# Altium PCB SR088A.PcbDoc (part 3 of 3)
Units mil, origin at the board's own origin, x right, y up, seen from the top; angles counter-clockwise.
Board outline 5010 x 3800 mil, 6 copper layers (Top Layer, Signal Layer 1, Signal Layer 2, Signal Layer 3, Signal Layer 4, Bottom Layer), stack 61.4 mil thick; 199 components, 82 nets, 478 pads, 1347 vias.
Unrouted connection lines stored in the file: 13.
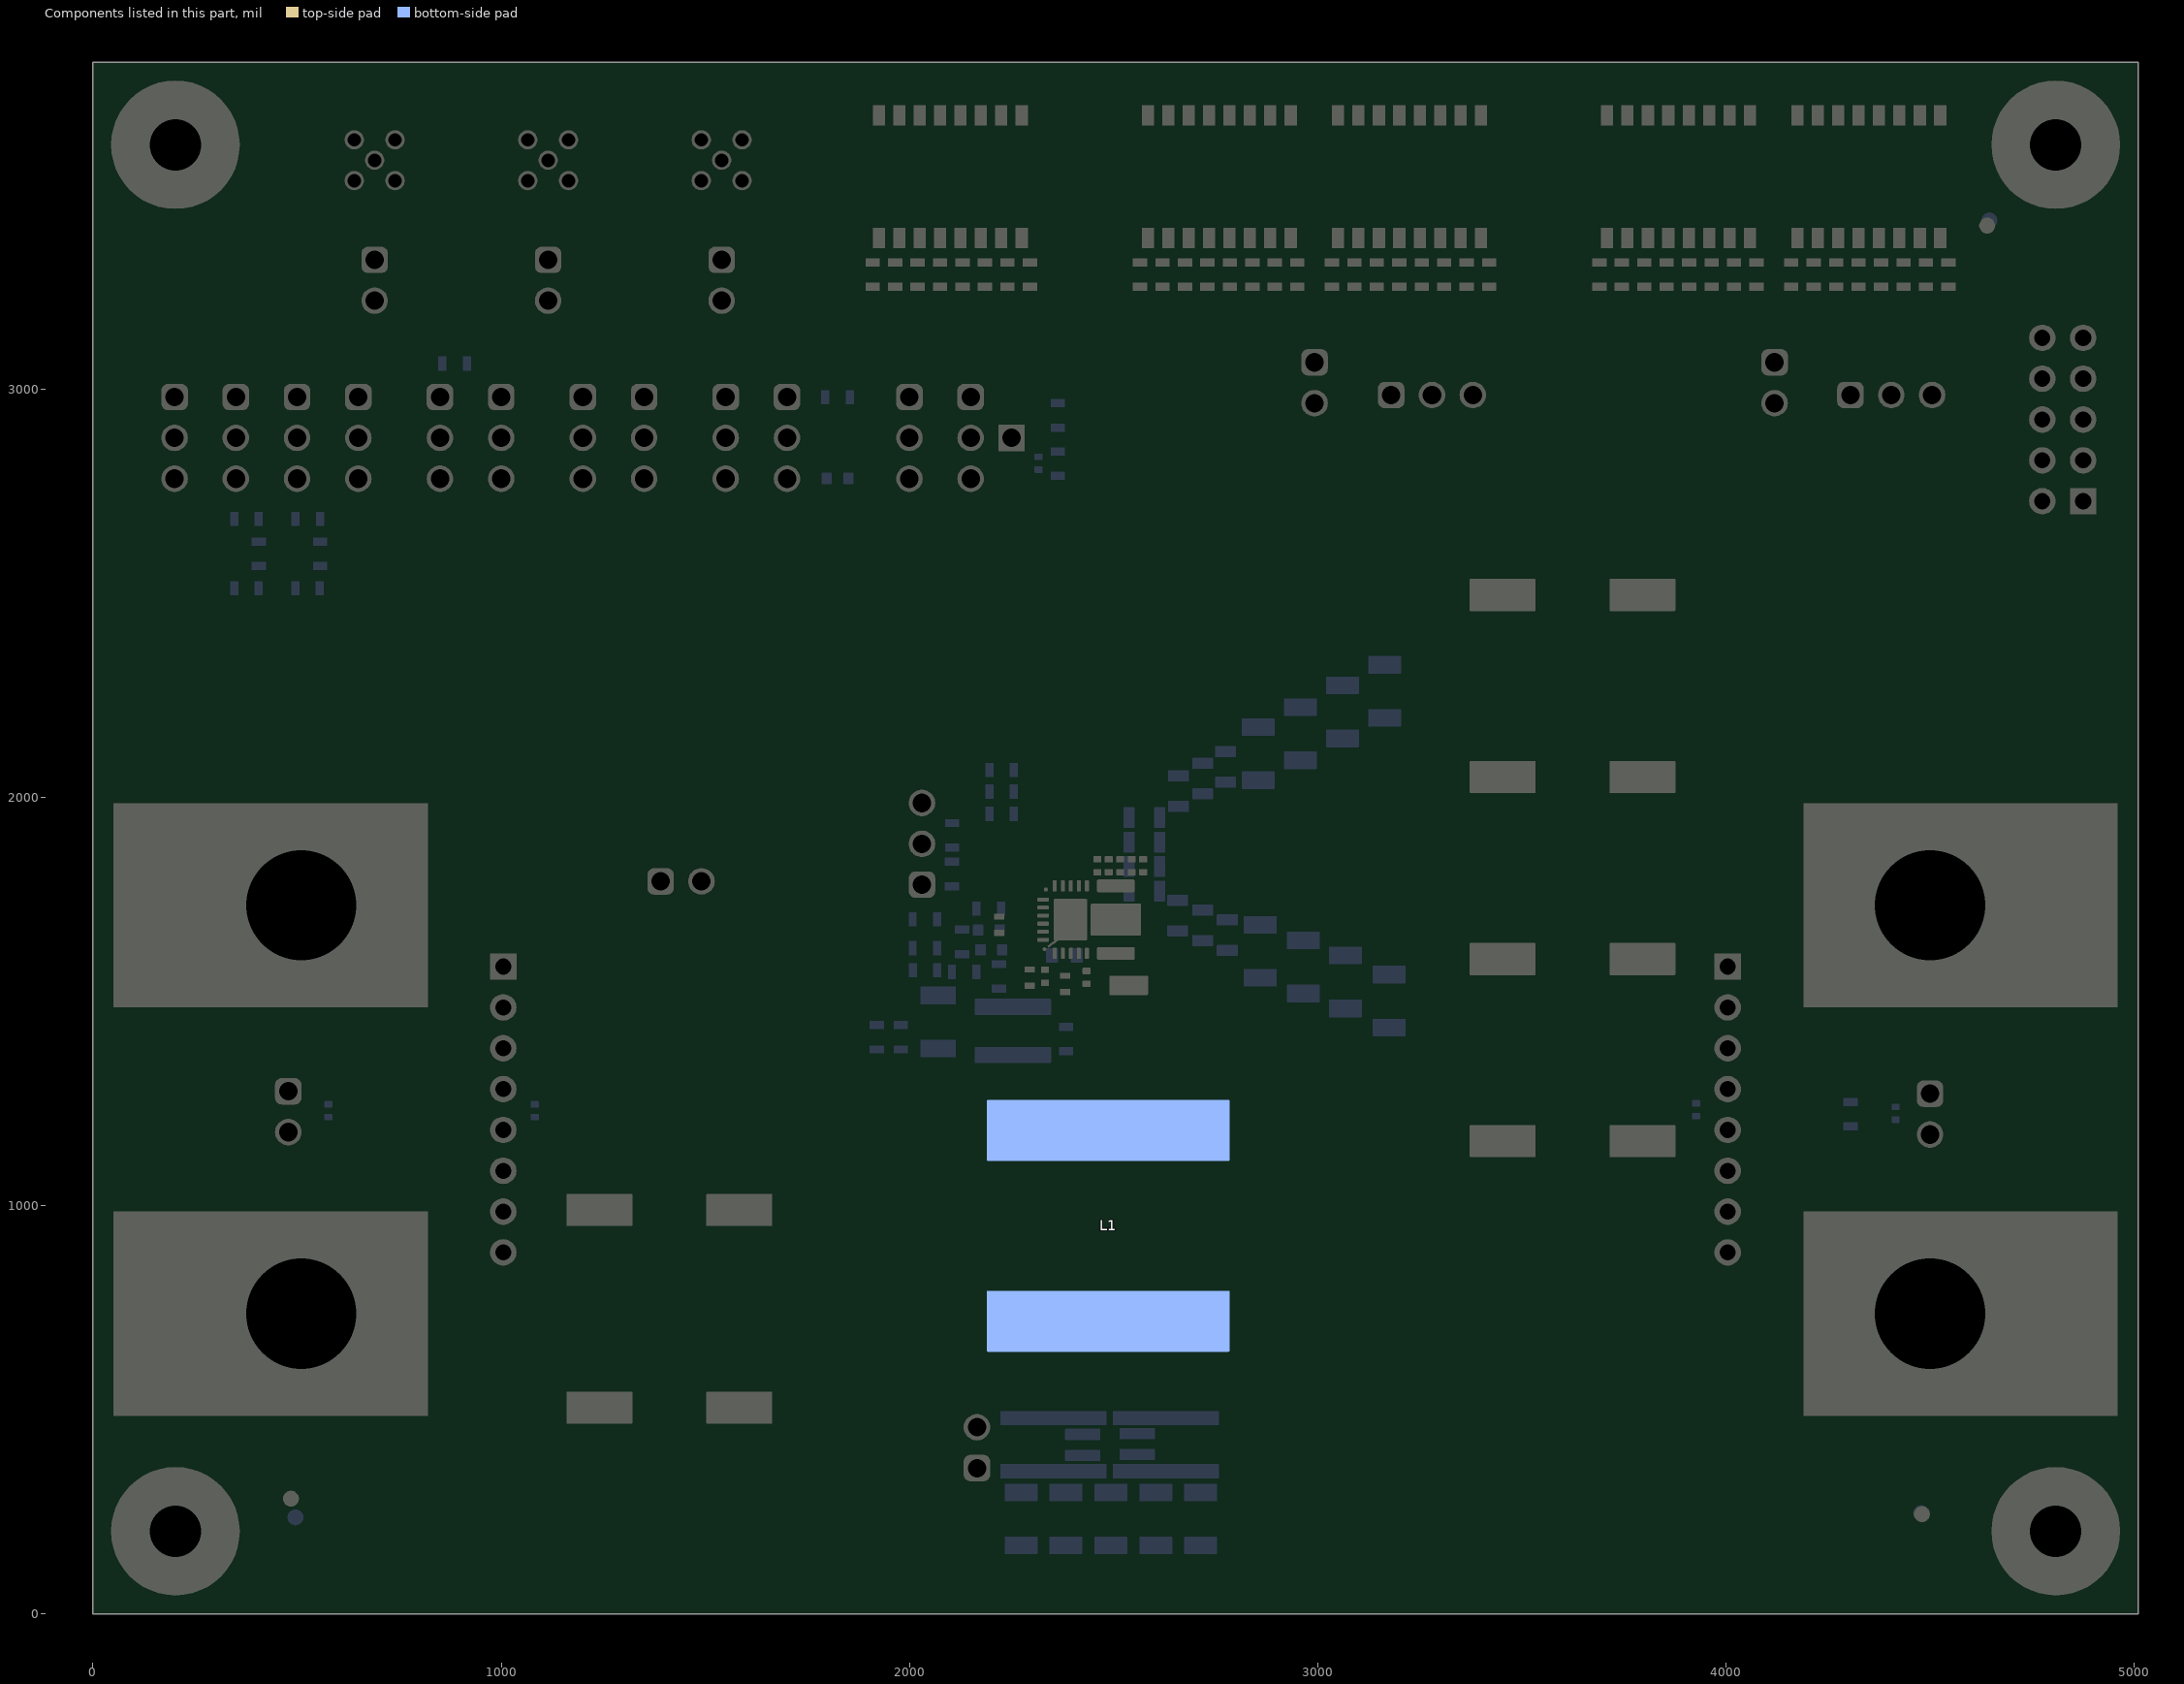
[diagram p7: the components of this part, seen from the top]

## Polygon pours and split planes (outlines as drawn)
AGND on Top Layer "TOP_LAYER_AGND_P178" (solid, remove dead copper, pour order 178): 2314.29,1632.94 2447.34,1632.22 2447.33,1536.55 2389.18,1478.22 2359.27,1478.19 2219.76,1338.59 1912.05,1338.59 1858.81,1391.83 1858.81,1623.43 1678.18,1804.07 1678.18,2015.39 1261.32,2432.24 25.49,2432.24 25.49,3774.23 4990.16,3774.23 4990.16,2670.21 2772.6,2670.21 2429.5,2327.11 2429.5,2024.51 2398.1,2024.51 2398.1,1761.45 2351.88,1761.45 2351.88,1651.86 2346.23,1646.21 2314.37,1646.21
VIN on Top Layer "TOP_LAYER_VIN_P143" (solid, pour order 143): 1178.25,2194.88 1777.67,1595.46 1777.67,1377.86 2766.5,407.08 2766.5,244.27 2738.76,216.54 2220.2,216.54 1541.95,397.36 1398.41,540.9 1398.41,1006.12 1161.72,1242.81 888.28,1242.81 0.91,1242.82 0.91,2194.88
SW on Top Layer "TOP_LAYER_SW_P133" (solid, remove dead copper, pour order 133): 2459.13,1621.28 2469.06,1631.22 2551.47,1631.22 2607.96,1574.72 2786.89,1292.8 2787.25,1293.16 2786.89,1111.04 2779.61,1103.77 2194.46,1103.77 2187.06,1111.16 2187.06,1248.1 2356.39,1417.43 2356.39,1439.65 2367.42,1450.68 2389.28,1450.68 2459.13,1520.17
VOUT on Top Layer "Top Layer-VOUT" (solid, pour order 110): 3688.9,1237.61 5019.69,1238.06 5019.69,2411.42 3700.81,2411.42 3543.33,2568.9 3365.98,2568.9 3216.91,2283.46 2639.16,1994.38 2602.34,1940.62 2602.34,1837.46 2589.18,1824.3 2450.49,1824.3 2450.49,1757.83 2567.39,1757.83 2843.71,1640 3365.98,1089.25 3540.54,1089.25
PGND on Top Layer "TOP_LAYER_AGND_P479" (solid, pour order 189): 0,3796.3 5010,3796.3 5010,0 0,0
PGND on Bottom Layer "TOP_LAYER_AGND_P479" (solid, remove dead copper, pour order 184): 3.77,3757.78 5014.63,3757.78 5014.63,-42.22 3.77,-42.22
L1 on Bottom Layer "Bottom Layer-L1" (solid, remove dead copper, pour order 147): 3033.74,464.54 3110.93,464.54 3204.02,557.62 3204.02,968.95 3102.17,1070.79 1926.64,1071.8 2083.7,617.19 2135.03,445.48 2168.17,424.21 2731.87,424.21 2787.35,368.74 2787.35,324.91 2850.14,262.12 2957.19,262.12 3014.56,319.49 3014.56,432.28 2839.45,607.48 2890.79,607.48
VIN on Bottom Layer "BOTTOM_LAYER_VIN_P152" (solid, remove dead copper, pour order 152): 1646.51,1743.24 2114.89,443.97 2174.34,404.01 2726.66,404.01 2766.5,364.17 2766.5,244.44 2738.6,216.54 2221.45,216.54 1539.15,396.81 1398.41,537.55 1398.41,1003.38 1159.8,1241.13 0,1241.13 0,2198 1191.75,2198
VOUT on Bottom Layer "Bottom Layer-VOUT" (solid, remove dead copper, pour order 175): 4990.16,1235.59 4990.16,2411.42 3700.79,2411.42 3545.85,2566.35 3365.84,2566.35 3216.91,2283.46 2592.96,1973.17 2580.05,1930.67 2580.05,1749.82 2981.24,1599.76 2981.24,1597.94 3326.88,1470.47 3954.83,1235.59
AGND on Bottom Layer "BOTTOM_LAYER_AGND_P176" (solid, remove dead copper, pour order 176): 2344.69,1598.7 2291.42,1598.7 2281.98,1589.26 2281.98,1575.53 2232.44,1526 2146.6,1526 2146.6,1392.58 2083.25,1329.22 1882.44,1329.22 1638.54,1990.29 1196.6,2432.24 21.81,2432.24 21.81,3778.03 4999.45,3778.03 4999.45,2674.02 2781.9,2674.02 2438.8,2330.92 2438.79,1957.14 2384.3,1902.64 2384.3,1801.92 2344.69,1762.32
VOUT on Bottom Layer "BOTTOM_LAYER_VOUT_P177" (solid, remove dead copper, pour order 177): 4076.03,1400.68 4076.03,2071.03 4104.28,2099.28 5010,2099.28 5010,1376.26 4100.46,1376.26
PGND on Bottom Layer "BOTTOM_LAYER_PGND_P182" (solid, remove dead copper, pour order 182): 4072.19,398.27 4072.19,1065.8 4105.94,1099.54 5004,1099.54 5004,366.53 4103.93,366.53
VIN on Bottom Layer "BOTTOM_LAYER_VIN_P183" (solid, remove dead copper, pour order 183): 931.81,2057.73 931.81,1402.79 885.47,1356.46 0,1356.46 0,2089.47 900.07,2089.47
PGND on Bottom Layer "BOTTOM_LAYER_PGND_P186" (solid, remove dead copper, pour order 186): 2558.39,1869.05 2446.5,1869.05 2446.5,1841.17 2558.39,1841.17
PGND on Bottom Layer "BOTTOM_LAYER_PGND_P187" (solid, remove dead copper, pour order 187): 931.81,398.27 931.81,1058.28 890.55,1099.54 0,1099.54 0,366.53 900.07,366.53
no net on Bottom Layer "BOTTOM_LAYER_NONET_P208" (solid, remove dead copper, pour order 208): 2319.14,770.02 2320.97,768.19 2320.97,590.5
SW on Signal Layer 2 "SIGNAL_LAYER_2_SW_P242" (solid, remove dead copper, pour order 242): 2227.4,1249.09 2204.6,1249.09 2204.6,1119.17 2227.4,1119.17
SW on Signal Layer 2 "SIGNAL_LAYER_2_SW_P240" (solid, remove dead copper, pour order 240): 2770.21,1249.09 2747.41,1249.09 2747.41,1119.17 2770.21,1119.17
SW on Signal Layer 2 "SIGNAL_LAYER_2_SW_P238" (solid, remove dead copper, pour order 238): 2339.73,1249.09 2297.57,1249.09 2297.57,1119.17 2339.73,1119.17
SW on Signal Layer 2 "SIGNAL_LAYER_2_SW_P237" (solid, remove dead copper, pour order 237): 2452.19,1249.09 2410.03,1249.09 2410.03,1119.17 2452.19,1119.17
SW on Signal Layer 2 "SIGNAL_LAYER_2_SW_P236" (solid, remove dead copper, pour order 236): 2564.65,1249.09 2522.49,1249.09 2522.49,1119.17 2564.65,1119.17
SW on Signal Layer 2 "SIGNAL_LAYER_2_SW_P235" (solid, remove dead copper, pour order 235): 2677.11,1249.09 2634.95,1249.09 2634.95,1119.17 2677.11,1119.17
PGND on Signal Layer 2 "Signal Layer 2-PGND" (solid, pour order 245): 5019.69,0 5019.69,2647.64 2781.22,2647.64 2671.32,2537.73 2671.32,2087.95 2612.35,2028.99 2612.35,1827.8 2517.55,1733.01 2517.55,1411.37 2425.08,1318.9 2104.77,1318.9 2064.58,1278.71 2064.58,686.12 2143.22,607.48 2411.59,607.48 2551.42,467.65 2551.42,369.39 2517.55,335.53 2144.01,335.53 1855.14,624.4 1855.14,1394.74 1055,2194.88 0.91,2194.88 0.91,0
PGND on Signal Layer 2 "SIGNAL_LAYER_2_PGND_P251" (solid, remove dead copper, pour order 251): 2258.7,185.99 2258.7,139.2 2757.6,139.2 2757.6,185.99
AGND on Signal Layer 2 "TOP_LAYER_AGND_P479" (solid, pour order 256): 21.81,3800 5010,3800 5010,0 21.81,0
PGND on Signal Layer 2 "SIGNAL_LAYER_2_PGND_P252" (solid, remove dead copper, pour order 252): 2444.53,1865.98 2456.75,1878.21 2546.19,1878.21 2558.65,1865.74 2558.65,1847.97 2546.17,1835.48 2457.53,1835.52 2444.53,1848.52
VOUT on Signal Layer 2 "Bottom Layer-VOUT" (solid, pour order 244): 5013.07,1241.66 4019.61,1241.66 3951.93,1253.26 3694.01,1253.26 3524.8,1084.05 3388.55,1084.05 3352.68,1119.93 3352.92,2530.34 3383.28,2560.7 3538.16,2560.93 3706.7,2392.38 5010,2392.38
PGND on Signal Layer 2 "SIGNAL_LAYER_2_PGND_P253" (solid, remove dead copper, pour order 253): 4076.3,394.16 4076.3,1065.94 4109.91,1099.54 5004,1099.54 5004,369.96 4100.5,369.96
VOUT on Signal Layer 2 "SIGNAL_LAYER_2_VOUT_P254" (solid, remove dead copper, pour order 254): 4076.03,1400.68 4076.03,2071.03 4101.13,2096.13 5010,2096.13 5010,1376.26 4100.46,1376.26
PGND on Signal Layer 2 "SIGNAL_LAYER_2_PGND_P255" (solid, remove dead copper, pour order 255): 931.81,398.27 931.81,1062.07 894.34,1099.54 0,1099.54 0,371.19 904.73,371.19
VIN on Signal Layer 2 "SIGNAL_LAYER_2_VIN_P243" (solid, remove dead copper, pour order 243): 931.81,2057.73 931.81,1402.79 885.47,1356.46 0,1356.46 0,2089.47 900.07,2089.47
SW on Signal Layer 3 "SIGNAL_LAYER_3_SW_P218" (solid, remove dead copper, pour order 218): 2227.4,1249.09 2204.6,1249.09 2204.6,1119.17 2227.4,1119.17
SW on Signal Layer 3 "SIGNAL_LAYER_3_SW_P217" (solid, remove dead copper, pour order 217): 2770.21,1249.09 2747.41,1249.09 2747.41,1119.17 2770.21,1119.17
SW on Signal Layer 3 "SIGNAL_LAYER_3_SW_P216" (solid, remove dead copper, pour order 216): 2339.73,1249.09 2297.57,1249.09 2297.57,1119.17 2339.73,1119.17
SW on Signal Layer 3 "SIGNAL_LAYER_3_SW_P215" (solid, remove dead copper, pour order 215): 2452.19,1249.09 2410.03,1249.09 2410.03,1119.17 2452.19,1119.17
SW on Signal Layer 3 "SIGNAL_LAYER_3_SW_P214" (solid, remove dead copper, pour order 214): 2564.65,1249.09 2522.49,1249.09 2522.49,1119.17 2564.65,1119.17
SW on Signal Layer 3 "SIGNAL_LAYER_3_SW_P213" (solid, remove dead copper, pour order 213): 2677.11,1249.09 2634.95,1249.09 2634.95,1119.17 2677.11,1119.17
AGND on Signal Layer 3 "TOP_LAYER_AGND_P479" (solid, pour order 262): 0,3800 5010,3800 5010,0 0,0
PGND on Signal Layer 3 "Signal Layer 3-PGND" (solid, remove dead copper, pour order 258): 0.91,0 5019.69,0 5019.69,2647.64 2781.22,2647.64 2671.87,2538.29 2671.87,2098.99 2444.21,1871.34 2444.21,1766.6 2433.57,1755.95 2364.52,1755.95 2352.32,1743.76 2352.32,1655.76 2357.44,1650.65 2452.36,1650.65 2517.56,1585.45 2517.55,1413.38 2423.07,1318.9 2104.32,1318.9 2064.58,1279.16 2064.58,686.12 2143.22,607.48 2411.59,607.48 2551.42,467.65 2551.42,369.39 2517.55,335.53 2143.22,335.53 1855.14,623.61 1855.14,1394.74 1055,2194.88 0.91,2194.88
PGND on Signal Layer 3 "SIGNAL_LAYER_3_PGND_P259" (solid, remove dead copper, pour order 259): 2444.53,1865.98 2456.75,1878.21 2546.19,1878.21 2558.65,1865.74 2558.65,1847.97 2546.17,1835.48 2457.53,1835.52 2444.53,1848.52
PGND on Signal Layer 3 "SIGNAL_LAYER_3_PGND_P260" (solid, remove dead copper, pour order 260): 4076.66,393.8 4076.66,1067.08 4109.12,1099.54 5004,1099.54 5004,369.96 4100.5,369.96
VOUT on Signal Layer 3 "SIGNAL_LAYER_3_VOUT_P257" (solid, remove dead copper, pour order 257): 4076.03,1400.68 4076.03,2071.03 4104.28,2099.28 5010,2099.28 5010,1376.26 4100.46,1376.26
PGND on Signal Layer 3 "SIGNAL_LAYER_3_PGND_P261" (solid, remove dead copper, pour order 261): 931.81,398.27 931.81,1061.4 893.67,1099.54 0,1099.54 0,370.86 904.4,370.86
VIN on Signal Layer 3 "SIGNAL_LAYER_3_VIN_P219" (solid, remove dead copper, pour order 219): 931.81,2057.73 931.81,1402.79 885.47,1356.46 0,1356.46 0,2089.47 900.07,2089.47
SW on Signal Layer 4 "SIGNAL_LAYER_4_SW_P231" (solid, remove dead copper, pour order 231): 2227.4,1249.09 2204.6,1249.09 2204.6,1119.17 2227.4,1119.17
SW on Signal Layer 4 "SIGNAL_LAYER_4_SW_P230" (solid, remove dead copper, pour order 230): 2770.21,1249.09 2747.41,1249.09 2747.41,1119.17 2770.21,1119.17
SW on Signal Layer 4 "SIGNAL_LAYER_4_SW_P229" (solid, remove dead copper, pour order 229): 2339.73,1249.09 2297.57,1249.09 2297.57,1119.17 2339.73,1119.17
SW on Signal Layer 4 "SIGNAL_LAYER_4_SW_P228" (solid, remove dead copper, pour order 228): 2452.19,1249.09 2410.03,1249.09 2410.03,1119.17 2452.19,1119.17
SW on Signal Layer 4 "SIGNAL_LAYER_4_SW_P227" (solid, remove dead copper, pour order 227): 2564.65,1249.09 2522.49,1249.09 2522.49,1119.17 2564.65,1119.17
SW on Signal Layer 4 "SIGNAL_LAYER_4_SW_P226" (solid, remove dead copper, pour order 226): 2677.11,1249.09 2634.95,1249.09 2634.95,1119.17 2677.11,1119.17
AGND on Signal Layer 4 "SIGNAL_LAYER_4_AGND_P263" (solid, remove dead copper, pour order 263): 1588.09,2438.79 25.49,2438.79 25.49,3774.23 4990.16,3774.23 4990.16,2670.21 1819.51,2670.21
PGND on Signal Layer 4 "TOP_LAYER_AGND_P479" (solid, remove dead copper, pour order 268): 0,3800 5010,3800 5010,0 0,0
PGND on Signal Layer 4 "SIGNAL_LAYER_4_PGND_P264" (solid, remove dead copper, pour order 264): 4072.19,398.27 4072.19,1065.8 4105.94,1099.54 5004,1099.54 5004,366.53 4103.93,366.53
VOUT on Signal Layer 4 "SIGNAL_LAYER_4_VOUT_P265" (solid, remove dead copper, pour order 265): 4076.03,1400.68 4076.03,2071.03 4104.28,2099.28 5010,2099.28 5010,1376.26 4100.46,1376.26
PGND on Signal Layer 4 "SIGNAL_LAYER_4_PGND_P266" (solid, remove dead copper, pour order 266): 931.81,398.27 931.81,1062.85 895.12,1099.54 0,1099.54 0,366.53 900.07,366.53
VIN on Signal Layer 4 "SIGNAL_LAYER_4_VIN_P267" (solid, remove dead copper, pour order 267): 931.81,2057.73 931.81,1402.79 885.47,1356.46 0,1356.46 0,2089.47 900.07,2089.47
SW on Signal Layer 1 "SIGNAL_LAYER_1_SW_P155" (solid, remove dead copper, pour order 155): 2677.11,1249.09 2634.95,1249.09 2634.95,1119.17 2677.11,1119.17
SW on Signal Layer 1 "SIGNAL_LAYER_1_SW_P161" (solid, remove dead copper, pour order 161): 2564.65,1249.09 2522.49,1249.09 2522.49,1119.17 2564.65,1119.17
SW on Signal Layer 1 "SIGNAL_LAYER_1_SW_P169" (solid, remove dead copper, pour order 169): 2452.19,1249.09 2410.03,1249.09 2410.03,1119.17 2452.19,1119.17
SW on Signal Layer 1 "SIGNAL_LAYER_1_SW_P197" (solid, remove dead copper, pour order 197): 2339.73,1249.09 2297.57,1249.09 2297.57,1119.17 2339.73,1119.17
SW on Signal Layer 1 "SIGNAL_LAYER_1_SW_P202" (solid, remove dead copper, pour order 202): 2770.21,1249.09 2747.41,1249.09 2747.41,1119.17 2770.21,1119.17
SW on Signal Layer 1 "SIGNAL_LAYER_1_SW_P203" (solid, remove dead copper, pour order 203): 2227.4,1249.09 2204.6,1249.09 2204.6,1119.17 2227.4,1119.17
PGND on Signal Layer 1 "SIGNAL_LAYER_1_PGND_P246" (solid, remove dead copper, pour order 246): 2550.84,1878.48 2451.36,1878.48 2444.22,1871.34 2444.22,1766.6 2433.57,1755.95 2364.52,1755.95 2352.32,1743.76 2352.32,1655.76 2357.44,1650.65 2530.99,1650.65 2560.17,1679.83 2560.54,1868.79
PGND on Signal Layer 1 "Signal Layer 1-PGND" (solid, pour order 247): 5019.69,0 5019.69,2647.64 2781.22,2647.64 2672.9,2539.32 2672.9,2100.03 2444.21,1871.34 2444.21,1658.79 2517.56,1585.45 2517.55,1411.61 2424.84,1318.9 2104.32,1318.9 2064.58,1279.16 2064.58,686.12 2143.22,607.48 2411.59,607.48 2551.42,467.65 2551.42,369.39 2517.55,335.53 2141.21,335.53 1855.12,621.62 1855.51,1394.38 1055,2194.88 0.91,2194.88 0.91,0
PGND on Signal Layer 1 "SIGNAL_LAYER_1_PGND_P249" (solid, remove dead copper, pour order 249): 4075.5,394.96 4075.5,1069.11 4105.94,1099.54 5004,1099.54 5004,369.96 4100.5,369.96
VOUT on Signal Layer 1 "SIGNAL_LAYER_1_VOUT_P204" (solid, remove dead copper, pour order 204): 4076.66,1400.05 4076.66,2071.66 4104.28,2099.28 5010,2099.28 5010,1376.26 4100.46,1376.26
PGND on Signal Layer 1 "SIGNAL_LAYER_1_PGND_P248" (solid, remove dead copper, pour order 248): 931.81,398.27 931.81,1059.68 891.95,1099.54 0,1099.54 0,371.19 904.73,371.19
VIN on Signal Layer 1 "SIGNAL_LAYER_1_VIN_P210" (solid, remove dead copper, pour order 210): 931.81,2057.73 931.81,1402.79 885.47,1356.46 0,1356.46 0,2089.47 900.07,2089.47
AGND on Signal Layer 1 "TOP_LAYER_AGND_P479" (solid, pour order 250): 0,3800 5010,3800 5010,0 0,0

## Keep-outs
Keep-Out Layer:
  text ".Layer_Name" at 577,-858.49 h60

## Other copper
Top Layer:
  pour cut-out: 3960.85,1184.78 ccw(c4004.42,1184.78) 4004.42,1141.21 ccw(c4004.42,1184.78) 4047.98,1184.78 ccw(c4004.42,1184.78) 4004.42,1228.35 ccw(c4004.42,1184.78)
  pour cut-out: 3915.68,1218 ccw(c3938.68,1218) 3938.68,1195 ccw(c3938.68,1218) 3961.68,1218 ccw(c3938.68,1218) 3938.68,1241 ccw(c3938.68,1218)
  pour cut-out: 3915.65,1251.14 ccw(c3938.65,1251.14) 3938.65,1228.14 ccw(c3938.65,1251.14) 3961.65,1251.14 ccw(c3938.65,1251.14) 3938.65,1274.14 ccw(c3938.65,1251.14)
  pour cut-out: 3960.95,1284.91 ccw(c4004.52,1284.91) 4004.52,1241.35 ccw(c4004.52,1284.91) 4048.08,1284.91 ccw(c4004.52,1284.91) 4004.52,1328.48 ccw(c4004.52,1284.91)
  pour cut-out: 960.99,1184.8 ccw(c1004.56,1184.8) 1004.56,1141.23 ccw(c1004.56,1184.8) 1048.12,1184.8 ccw(c1004.56,1184.8) 1004.56,1228.37 ccw(c1004.56,1184.8)
  pour cut-out: 960.99,1284.8 ccw(c1004.56,1284.8) 1004.56,1241.23 ccw(c1004.56,1284.8) 1048.12,1284.8 ccw(c1004.56,1284.8) 1004.56,1328.37 ccw(c1004.56,1284.8)
  pour cut-out: 1059.35,1218.41 ccw(c1082.35,1218.41) 1082.35,1195.41 ccw(c1082.35,1218.41) 1105.35,1218.41 ccw(c1082.35,1218.41) 1082.35,1241.41 ccw(c1082.35,1218.41)
  pour cut-out: 1059.23,1251.41 ccw(c1082.23,1251.41) 1082.23,1228.41 ccw(c1082.23,1251.41) 1105.23,1251.41 ccw(c1082.23,1251.41) 1082.23,1274.41 ccw(c1082.23,1251.41)
  pour cut-out: -23,0 ccw(c0,0) 0,-23 ccw(c0,0) 23,0 ccw(c0,0) 0,23 ccw(c0,0)
  pour cut-out: 3964.55,1274.85 3937.18,1256.03 3957.27,1235.94 4037.13,1235.94 4016.72,1280.62
  pour cut-out: 2328.76,1628.83 2349.99,1628.83 2349.99,1626.6 2328.76,1626.6
  pour cut-out: 2439.29,1765.13 2439.29,1756.09 2356.91,1756.09 2351.88,1751.06 2351.88,1647.69 2343.55,1647.69 2343.55,1765.13
  pour cut-out: 2351.88,1650.71 2359.29,1643.3 2457.31,1643.3 2457.31,1631.73 2351.88,1631.73
  pour cut-out: 2232.63,1605.84 2220.36,1618.11 2233.07,1639.46 2233.07,1686.14 2281.96,1686.14 2281.96,1605.84
  pour cut-out: 2197.88,1698.55 2197.88,1684.74 2207.88,1674.75 2238.34,1674.75 2238.34,1698.43
  text ".Layer_Name" at 577,-858.49 h60
Signal Layer 1:
  pour cut-out: 3960.95,1284.91 ccw(c4004.52,1284.91) 4004.52,1241.35 ccw(c4004.52,1284.91) 4048.08,1284.91 ccw(c4004.52,1284.91) 4004.52,1328.48 ccw(c4004.52,1284.91)
  pour cut-out: 3960.85,1184.78 ccw(c4004.42,1184.78) 4004.42,1141.21 ccw(c4004.42,1184.78) 4047.98,1184.78 ccw(c4004.42,1184.78) 4004.42,1228.35 ccw(c4004.42,1184.78)
  pour cut-out: 3915.68,1218 ccw(c3938.68,1218) 3938.68,1195 ccw(c3938.68,1218) 3961.68,1218 ccw(c3938.68,1218) 3938.68,1241 ccw(c3938.68,1218)
  pour cut-out: 3915.65,1251.14 ccw(c3938.65,1251.14) 3938.65,1228.14 ccw(c3938.65,1251.14) 3961.65,1251.14 ccw(c3938.65,1251.14) 3938.65,1274.14 ccw(c3938.65,1251.14)
  pour cut-out: 960.99,1184.8 ccw(c1004.56,1184.8) 1004.56,1141.23 ccw(c1004.56,1184.8) 1048.12,1184.8 ccw(c1004.56,1184.8) 1004.56,1228.37 ccw(c1004.56,1184.8)
  pour cut-out: 1059.23,1251.41 ccw(c1082.23,1251.41) 1082.23,1228.41 ccw(c1082.23,1251.41) 1105.23,1251.41 ccw(c1082.23,1251.41) 1082.23,1274.41 ccw(c1082.23,1251.41)
  pour cut-out: 1059.35,1218.41 ccw(c1082.35,1218.41) 1082.35,1195.41 ccw(c1082.35,1218.41) 1105.35,1218.41 ccw(c1082.35,1218.41) 1082.35,1241.41 ccw(c1082.35,1218.41)
  pour cut-out: 4984.51,370.2 4984.51,25.49 4665.51,25.49 4665.51,120.7
  pour cut-out: 25.49,376.98 25.49,25.49 344.49,25.49 344.49,127.47
  text ".Layer_Name" at 577,-858.49 h60
Signal Layer 2:
  pour cut-out: 2212.37,182.05 ccw(c2235.37,182.05) 2235.37,159.05 ccw(c2235.37,182.05) 2258.37,182.05 ccw(c2235.37,182.05) 2235.37,205.05 ccw(c2235.37,182.05)
  pour cut-out: 3960.85,1184.78 ccw(c4004.42,1184.78) 4004.42,1141.21 ccw(c4004.42,1184.78) 4047.98,1184.78 ccw(c4004.42,1184.78) 4004.42,1228.35 ccw(c4004.42,1184.78)
  pour cut-out: 3960.95,1284.91 ccw(c4004.52,1284.91) 4004.52,1241.35 ccw(c4004.52,1284.91) 4048.08,1284.91 ccw(c4004.52,1284.91) 4004.52,1328.48 ccw(c4004.52,1284.91)
  pour cut-out: 3915.68,1218 ccw(c3938.68,1218) 3938.68,1195 ccw(c3938.68,1218) 3961.68,1218 ccw(c3938.68,1218) 3938.68,1241 ccw(c3938.68,1218)
  pour cut-out: 3915.65,1251.14 ccw(c3938.65,1251.14) 3938.65,1228.14 ccw(c3938.65,1251.14) 3961.65,1251.14 ccw(c3938.65,1251.14) 3938.65,1274.14 ccw(c3938.65,1251.14)
  pour cut-out: 960.99,1184.8 ccw(c1004.56,1184.8) 1004.56,1141.23 ccw(c1004.56,1184.8) 1048.12,1184.8 ccw(c1004.56,1184.8) 1004.56,1228.37 ccw(c1004.56,1184.8)
  pour cut-out: 1059.35,1218.41 ccw(c1082.35,1218.41) 1082.35,1195.41 ccw(c1082.35,1218.41) 1105.35,1218.41 ccw(c1082.35,1218.41) 1082.35,1241.41 ccw(c1082.35,1218.41)
  pour cut-out: 1059.23,1251.41 ccw(c1082.23,1251.41) 1082.23,1228.41 ccw(c1082.23,1251.41) 1105.23,1251.41 ccw(c1082.23,1251.41) 1082.23,1274.41 ccw(c1082.23,1251.41)
  pour cut-out: 3960.32,1184.8 ccw(c4003.89,1184.8) 4003.89,1141.23 ccw(c4003.89,1184.8) 4047.45,1184.8 ccw(c4003.89,1184.8) 4003.89,1228.37 ccw(c4003.89,1184.8)
  pour cut-out: 3969.31,1278.61 3952.84,1269.27 3922.43,1267.36 3907.65,1252.58 3907.65,1232.55 4004.19,1161.73 4060.53,1233.22 4027.26,1279.43
  pour cut-out: 2612.57,1858.54 2612.57,1997.01 2591.7,1997.07 2591.7,1841.57 2491.5,1741.08 2512.97,1709.01 2547.82,1709.01 2576.57,1732.27 2612.57,1732.27 2612.57,1828.9
  pour cut-out: 4984.51,370.2 4984.51,25.49 4665.51,25.49 4665.51,120.7
  pour cut-out: 25.49,376.98 25.49,25.49 344.49,25.49 344.49,127.47
  pour cut-out: 2365.8,1812.56 2312.11,1758.87 2312.11,1638.32 2329.34,1621.08 2329.34,1596.27 2330.04,1596.97 2360.93,1596.97 2360.93,1633.77 2361.11,1633.94 2346.09,1648.96 2346.09,1748.6 2387.32,1789.83 2387.32,1792.25
  pour cut-out: 2354.97,1754.88 2460.08,1754.88 2460.08,1640.99 2355.47,1640.99
  text ".Layer_Name" at 577,-858.49 h60
Signal Layer 3:
  pour cut-out: 3915.65,1251.14 ccw(c3938.65,1251.14) 3938.65,1228.14 ccw(c3938.65,1251.14) 3961.65,1251.14 ccw(c3938.65,1251.14) 3938.65,1274.14 ccw(c3938.65,1251.14)
  pour cut-out: 3915.68,1218 ccw(c3938.68,1218) 3938.68,1195 ccw(c3938.68,1218) 3961.68,1218 ccw(c3938.68,1218) 3938.68,1241 ccw(c3938.68,1218)
  pour cut-out: 3960.85,1184.78 ccw(c4004.42,1184.78) 4004.42,1141.21 ccw(c4004.42,1184.78) 4047.98,1184.78 ccw(c4004.42,1184.78) 4004.42,1228.35 ccw(c4004.42,1184.78)
  pour cut-out: 3960.95,1284.91 ccw(c4004.52,1284.91) 4004.52,1241.35 ccw(c4004.52,1284.91) 4048.08,1284.91 ccw(c4004.52,1284.91) 4004.52,1328.48 ccw(c4004.52,1284.91)
  pour cut-out: 960.99,1184.8 ccw(c1004.56,1184.8) 1004.56,1141.23 ccw(c1004.56,1184.8) 1048.12,1184.8 ccw(c1004.56,1184.8) 1004.56,1228.37 ccw(c1004.56,1184.8)
  pour cut-out: 1059.23,1251.41 ccw(c1082.23,1251.41) 1082.23,1228.41 ccw(c1082.23,1251.41) 1105.23,1251.41 ccw(c1082.23,1251.41) 1082.23,1274.41 ccw(c1082.23,1251.41)
  pour cut-out: 1059.35,1218.41 ccw(c1082.35,1218.41) 1082.35,1195.41 ccw(c1082.35,1218.41) 1105.35,1218.41 ccw(c1082.35,1218.41) 1082.35,1241.41 ccw(c1082.35,1218.41)
  pour cut-out: 4984.51,370.2 4984.51,25.49 4665.51,25.49 4665.51,120.7
  pour cut-out: 25.49,376.98 25.49,25.49 344.49,25.49 344.49,127.47
  text ".Layer_Name" at 577,-858.49 h60
Signal Layer 4:
  pour cut-out: 3915.65,1251.14 ccw(c3938.65,1251.14) 3938.65,1228.14 ccw(c3938.65,1251.14) 3961.65,1251.14 ccw(c3938.65,1251.14) 3938.65,1274.14 ccw(c3938.65,1251.14)
  pour cut-out: 3915.68,1218 ccw(c3938.68,1218) 3938.68,1195 ccw(c3938.68,1218) 3961.68,1218 ccw(c3938.68,1218) 3938.68,1241 ccw(c3938.68,1218)
  pour cut-out: 3960.85,1184.78 ccw(c4004.42,1184.78) 4004.42,1141.21 ccw(c4004.42,1184.78) 4047.98,1184.78 ccw(c4004.42,1184.78) 4004.42,1228.35 ccw(c4004.42,1184.78)
  pour cut-out: 3960.95,1284.91 ccw(c4004.52,1284.91) 4004.52,1241.35 ccw(c4004.52,1284.91) 4048.08,1284.91 ccw(c4004.52,1284.91) 4004.52,1328.48 ccw(c4004.52,1284.91)
  pour cut-out: 1059.23,1251.41 ccw(c1082.23,1251.41) 1082.23,1228.41 ccw(c1082.23,1251.41) 1105.23,1251.41 ccw(c1082.23,1251.41) 1082.23,1274.41 ccw(c1082.23,1251.41)
  pour cut-out: 1059.35,1218.41 ccw(c1082.35,1218.41) 1082.35,1195.41 ccw(c1082.35,1218.41) 1105.35,1218.41 ccw(c1082.35,1218.41) 1082.35,1241.41 ccw(c1082.35,1218.41)
  pour cut-out: 960.99,1184.8 ccw(c1004.56,1184.8) 1004.56,1141.23 ccw(c1004.56,1184.8) 1048.12,1184.8 ccw(c1004.56,1184.8) 1004.56,1228.37 ccw(c1004.56,1184.8)
  pour cut-out: 3960.95,1184.91 ccw(c4004.52,1184.91) 4004.52,1141.35 ccw(c4004.52,1184.91) 4048.08,1184.91 ccw(c4004.52,1184.91) 4004.52,1228.48 ccw(c4004.52,1184.91)
  pour cut-out: 3960.95,1284.91 ccw(c4004.52,1284.91) 4004.52,1241.35 ccw(c4004.52,1284.91) 4048.08,1284.91 ccw(c4004.52,1284.91) 4004.52,1328.48 ccw(c4004.52,1284.91)
  text ".Layer_Name" at 577,-858.49 h60
Bottom Layer:
  pour cut-out: 3915.65,1251.14 ccw(c3938.65,1251.14) 3938.65,1228.14 ccw(c3938.65,1251.14) 3961.65,1251.14 ccw(c3938.65,1251.14) 3938.65,1274.14 ccw(c3938.65,1251.14)
  pour cut-out: 3915.68,1218 ccw(c3938.68,1218) 3938.68,1195 ccw(c3938.68,1218) 3961.68,1218 ccw(c3938.68,1218) 3938.68,1241 ccw(c3938.68,1218)
  pour cut-out: 3960.85,1184.78 ccw(c4004.42,1184.78) 4004.42,1141.21 ccw(c4004.42,1184.78) 4047.98,1184.78 ccw(c4004.42,1184.78) 4004.42,1228.35 ccw(c4004.42,1184.78)
  pour cut-out: 3960.95,1284.91 ccw(c4004.52,1284.91) 4004.52,1241.35 ccw(c4004.52,1284.91) 4048.08,1284.91 ccw(c4004.52,1284.91) 4004.52,1328.48 ccw(c4004.52,1284.91)
  pour cut-out: 3960.85,1184.78 ccw(c4004.42,1184.78) 4004.42,1141.21 ccw(c4004.42,1184.78) 4047.98,1184.78 ccw(c4004.42,1184.78) 4004.42,1228.35 ccw(c4004.42,1184.78)
  pour cut-out: 3960.95,1284.91 ccw(c4004.52,1284.91) 4004.52,1241.35 ccw(c4004.52,1284.91) 4048.08,1284.91 ccw(c4004.52,1284.91) 4004.52,1328.48 ccw(c4004.52,1284.91)
  pour cut-out: 3915.68,1218 ccw(c3938.68,1218) 3938.68,1195 ccw(c3938.68,1218) 3961.68,1218 ccw(c3938.68,1218) 3938.68,1241 ccw(c3938.68,1218)
  pour cut-out: 3915.65,1251.14 ccw(c3938.65,1251.14) 3938.65,1228.14 ccw(c3938.65,1251.14) 3961.65,1251.14 ccw(c3938.65,1251.14) 3938.65,1274.14 ccw(c3938.65,1251.14)
  pour cut-out: 962.53,1183.95 ccw(c1006.1,1183.95) 1006.1,1140.38 ccw(c1006.1,1183.95) 1049.66,1183.95 ccw(c1006.1,1183.95) 1006.1,1227.51 ccw(c1006.1,1183.95)
  pour cut-out: 1059.35,1218.41 ccw(c1082.35,1218.41) 1082.35,1195.41 ccw(c1082.35,1218.41) 1105.35,1218.41 ccw(c1082.35,1218.41) 1082.35,1241.41 ccw(c1082.35,1218.41)
  pour cut-out: 1059.23,1251.41 ccw(c1082.23,1251.41) 1082.23,1228.41 ccw(c1082.23,1251.41) 1105.23,1251.41 ccw(c1082.23,1251.41) 1082.23,1274.41 ccw(c1082.23,1251.41)
  pour cut-out: 3961.68,1185.1 ccw(c4005.25,1185.1) 4005.25,1141.54 ccw(c4005.25,1185.1) 4048.81,1185.1 ccw(c4005.25,1185.1) 4005.25,1228.67 ccw(c4005.25,1185.1)
  pour cut-out: 3961.68,1285.1 ccw(c4005.25,1285.1) 4005.25,1241.54 ccw(c4005.25,1285.1) 4048.81,1285.1 ccw(c4005.25,1285.1) 4005.25,1328.67 ccw(c4005.25,1285.1)
  pour cut-out: 962.53,1283.95 ccw(c1006.1,1283.95) 1006.1,1240.38 ccw(c1006.1,1283.95) 1049.66,1283.95 ccw(c1006.1,1283.95) 1006.1,1327.51 ccw(c1006.1,1283.95)
  pour cut-out: 3964.55,1274.85 3937.18,1256.03 3959.74,1233.47 4038.25,1233.47 4016.72,1280.62
  pour cut-out: 1059.26,1252.29 1105.21,1252.29 1105.21,1218.41 1059.42,1218.41
  pour cut-out: 3905.13,1258.42 3920.87,1274.17 3938.09,1274.17 3938.09,1195.03 3921.37,1195.03 3905.13,1211.27
  pour cut-out: 967.25,1239.92 1046.69,1239.92 1046.69,1220.7 961.27,1220.7
  pour cut-out: 1987.95,1570.15 1987.95,1616.61 2000.83,1616.61 2016.13,1601.31 2077.25,1601.31 2077.25,1585.63 2029.92,1538.31 2019.8,1538.31
  pour cut-out: 2497.84,495.97 2483.61,495.97 2483.61,331.47 2497.84,331.47
  pour cut-out: 3073.1,1110.78 3082.08,1119.76 3153.26,1048.58 3144.28,1039.6
  pour cut-out: 1993.33,1636.38 1993.33,1657.42 2031.62,1657.42 2081.26,1657.42 2081.26,1630.26 2053.42,1602.42 2027.29,1602.42
  pour cut-out: 2144.59,1550.24 2144.59,1565.88 2249.67,1565.88 2249.67,1555.93 2234.71,1540.97 2153.86,1540.97
  pour cut-out: 2314.6,1758.95 2314.6,1621.34 2344.29,1622.7 2344.29,1758.95
  pour cut-out: 2369.09,1812.45 2389.24,1792.3 2335.25,1738.3 2314.6,1758.95
  pour cut-out: 2356.23,1545.88 2387.61,1545.88 2387.61,1538.08 2356.23,1538.09
  pour cut-out: 2179.86,1754.44 2211.24,1754.44 2211.24,1746.64 2179.86,1746.64
  pour cut-out: 2186.96,1653.8 2211.91,1653.8 2211.91,1608.72 2186.96,1608.72
  pour cut-out: 2423.55,1192.03 2454.94,1192.03 2454.94,1184.24 2423.55,1184.24
  pour cut-out: 2333.81,1630.76 2365.2,1630.76 2365.2,1622.97 2333.81,1622.97
  text ".Layer_Name" at 577,-858.49 h60

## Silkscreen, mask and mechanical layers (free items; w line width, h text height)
Top Overlay:
  lines w10: 145.52,2219.83 144.81,2071.48 773.47,2071.48 ; 146.16,2221.73 774.82,2221.73 ; 197.94,2676.25 197.94,2711.5 ; 199.94,2674.25 376.81,2674.25 ; 329.94,2674.25 889.94,2674.25 ; 347.94,2676.25 347.94,2711.5 ; 499.99,2677.99 499.99,2711.5 ; 649.72,2674.25 649.72,2711.5 ; 774.13,2072.82 774.85,2221.17 ; 829.72,2674.25 1026.3,2674.25 ; 849.72,2674.25 849.72,2711.5 ; 997.72,2674.25 997.72,2711.5 ; 1009.61,2674.2 1548.8,2674.2 ; 1199.72,2674.25 1199.72,2711.5 ; 1346.72,2674.25 1346.72,2711.5 ; 1549.72,2674.25 1549.72,2711.5 ; 1998.72,2674.25 1998.72,2711.5 ; 1998.94,2674.25 2148.94,2674.25 ; 2148.72,2674.25 2148.72,2711.5 ; 4259.66,2219.83 4258.94,2071.48 4853.09,2071.48 ; 4260.29,2221.73 4852.09,2221.73 ; 4853.27,2072.82 4853.98,2221.17
  text "ATRK" at 640,3722.84 h30
  text "SYNCIN" at 1022.6,3722.84 h30
  text "SYNCOUT" at 1446.85,3722.84 h30
  text "CFG0" at 2150.04,3722.84 h30
  text "CFG1" at 2935,3722.84 h30
  text "CFG2" at 4055.12,3722.84 h30
  text "ATRK" at 511.58,3299.75 h30
  text "SYNCIN" at 881.6,3299.75 h30
  text "SYNCOUT" at 1271.61,3299.75 h30
  text "AGND" at 511.58,3200.1 h30
  text "AGND" at 936.58,3200.1 h30
  text "AGND" at 1361.58,3200.09 h30
  text "SS" at 177.25,3101.5 h30
  text "IMON" at 291.94,3101.5 h30
  text "COMP" at 449.95,3101.5 h30
  text "RT" at 624.54,3101.5 h30
  text "PGOOD" at 851.86,3101.5 h30
  text "MODE" at 1205,3101.5 h30
  text "DLY" at 1586.6,3101.5 h30
  text "EN/UVLO" at 1983.76,3097.5 h30
  text "CFG1" at 2824.8,3048.76 h30
  text "CFG2" at 3937.01,3048.76 h30
  text "Sig-" at 31.3,2992.31 h30
  text "AGND" at 2814.96,2949.53 h30
  text "AGND" at 3937.01,2949.53 h30
  text "nal" at 31.3,2941.11 h30
  text "VIN" at 2260.01,2939.02 h30 r90
  text "VCC" at 1098.76,2930.16 h30 r90
  text "AGND" at 1812.18,2926.58 h30 r90
  text "FPWM" at 1446.94,2905.17 h30 r90
  text "Sig-" at 31.3,2878.31 h30
  text "0.34*VIN" at 2318.48,2863.6 h30
  text "SCL" at 3391.68,2834.03 h30 r90
  text "SDA" at 4516.09,2834.03 h30 r90
  text "nal" at 31.3,2827.11 h30
  text "CFG1" at 3293.24,2814.04 h30 r90
  text "CFG2" at 4419.13,2804.04 h30 r90
  text "S2/S3" at 3196.24,2774.05 h30 r90
  text "S4/S5" at 4319.45,2774.05 h30 r90
  text "AGND" at 28.06,2757.17 h30
  text "DE" at 1444.67,2755.45 h30 r90
  text "AGND" at 1099.71,2743.15 h30 r90
  text "CAP" at 1812.18,2738.87 h30 r90
  text "AGND" at 2255.67,2703.78 h30 r90
  text "AGND" at 2021.2,2624.86 h30
  text "AGND" at 697.19,2623.06 h30
  text "JUMPER" at 1018.22,2469.27 h30 r90
  text "JUMPER" at 1368.37,2469.27 h30 r90
  text "JUMPER" at 2214.56,2469.27 h30 r90
  text "JUMPER" at 1706.1,2465.72 h30 r90
  text "30A MAX" at 201.95,2105.68 h80
  text "15A MAX" at 4312.57,2105.68 h80
  text "JP8" at 2030.69,2070.58 h30 r90
  text "ATRK" at 1851.13,1996.73 h30
  text "EXT" at 1881.12,1948.33 h30
  text "ATRK" at 1851.13,1870.68 h30
  text "VIN" at 1233.36,1785.7 h30
  text "BIAS" at 1575.35,1784.22 h30
  text "24V" at 1881.12,1770.71 h30
  text "VIN" at 887.96,1703.51 h30 r90
  text "VOUT" at 4128.64,1688.89 h30 r90
  text "VIN" at 1108.01,1449.87 h30 r90
  text "VOUT" at 3930.29,1433.46 h30 r90
  text "S+" at 1106.25,1282.35 h30 r90
  text "S+" at 3932.32,1278.9 h30 r90
  text "S-" at 3930.91,1176.66 h30 r90
  text "S-" at 1107.56,1141.23 h30 r90
  text "GND" at 3930.34,946.73 h30 r90
  text "GND" at 1109.6,940.94 h30 r90
  text "GND" at 4148.64,684.37 h30 r90
  text "GND" at 870.96,683.44 h30 r90
  text ".PRJ_Number" at 3438.88,581.89 h60
  text "REV. .PCB_Rev" at 3438.88,485.5 h40
  text "L1" at 2035.62,438.56 h30
  text "VIN" at 2000.64,339.5 h30
  text ".Layer_Name" at 577,-858.49 h60
Bottom Overlay:
  lines w8: 2101.68,548.33 2901.68,548.33
  text "ATRK" at 1970.4,1988.48 h30
  text "EXT" at 1970.4,1946.31 h30
  text "ATRK" at 1970.73,1863.91 h30
  text "24V" at 1970.57,1763.26 h30
  text "CUT  HERE" at 2601.82,562.48 h30
  text ".Layer_Name" at 577,-858.49 h60
Top Paste:
  text ".Layer_Name" at 577,-858.49 h60
Bottom Paste:
  text ".Layer_Name" at 577,-858.49 h60
Top Solder:
  text ".Layer_Name" at 577,-858.49 h60
  text ".Layer_Name" at 577,-858.49 h60
Bottom Solder:
  text ".Layer_Name" at 577,-858.49 h60
Drill Guide:
  text ".Layer_Name" at 577,-858.49 h60
M1 Board Outline:
  the board outline again, w10
  text ".Layer_Name" at 577,-858.49 h60
M2 Board Dimensions:
  rectangle: 0,-275 125,-150
  rectangle: 125,-400 500,-275
  lines w7: 0,-275 1000,-275 ; 125,-400 125,-150 ; 250,-400 250,-150 ; 500,-400 500,-150 ; 750,-400 750,-150 ; 0,-400 1000,-400 1000,-150 0,-150 0,-400
  text ".Layer_Name" at 577,-858.49 h60
M3 3D STEP Top:
  text ".Layer_Name" at 577,-858.49 h60
M4 3D STEP Bottom:
  text ".Layer_Name" at 577,-858.49 h60
M5 Assembly Top:
  lines w10: -292,-930.17 6308,-930.17 ; -292,-726.83 6310,-726.83 ; -292,-523.5 -292,-1133.5 3713,-1133.5 6310,-1133.5 6310,-523.5 -291.5,-523.5 -291.5,-1133.5 1284,-1133.5 ; 2173,-1133.5 2173,-523.5 ; 3440,-726.83 3440,-523.5 ; 4280,-726.83 4280,-523.5 ; 4902,-1140 4902,-937.17
  text "COMPONENTS MARKED 'DNP' SHOULD NOT BE POPULATED." at 1153.5,-318.5 h60
  text "ASSEMBLY VARIANT:" at 1153,-434 h60
  text ".VariantName" at 2189,-434 h60
  text "PCB VIEWED FROM TOP SIDE" at -228.5,-655.67 h60
  text "BOARD #:" at 2248,-655.67 h60
  text ".PRJ_Number" at 2793.5,-655.67 h60
  text "REV:" at 3638,-655.67 h60
  text ".PCB_Rev" at 3929.5,-655.67 h60
  text "SVN REV:" at 4476,-655.67 h60
  text ".VersionControl_RevNumber" at 4982,-655.67 h60
  text "TID #:" at 2248,-859 h60
  text ".TID" at 2793.5,-859 h60
  text "PLOT NAME =" at -228.5,-1064.34 h60
  text ".plot_File_Name" at 577,-1064.34 h60
  text "GENERATED    :" at 2250,-1064.34 h60
  text ".Print_Date" at 3119.5,-1064.34 h60
  text ".Print_Time" at 3848.5,-1064.34 h60
  text "TEXAS INSTRUMENTS" at 5113,-1064.34 h60
M6 Assembly Bottom:
  lines w10: -292.5,-727.33 6309.5,-727.33 ; -290.5,-930.67 6309.5,-930.67 ; 1115.5,-1140.5 1115.5,-937.67 ; 1737.5,-727.33 1737.5,-524 ; 2577.5,-727.33 2577.5,-524 ; 3844.5,-1134 3844.5,-524 ; 4733.5,-1134 6309,-1134 6309,-524 -292.5,-524 -292.5,-1134 2304.5,-1134 6309.5,-1134 6309.5,-524
  text "COMPONENTS MARKED 'DNP' SHOULD NOT BE POPULATED." at 6102,-318 h60
  text ".VariantName" at 5058,-434 h60
  text "ASSEMBLY VARIANT:" at 6097,-434 h60
  text ".VersionControl_RevNumber" at 1035.5,-656.17 h60
  text "SVN REV:" at 1541.5,-656.17 h60
  text ".PCB_Rev" at 2088,-656.17 h60
  text "REV:" at 2379.5,-656.17 h60
  text ".PRJ_Number" at 3224,-656.17 h60
  text "BOARD #:" at 3769.5,-656.17 h60
  text "PCB VIEWED FROM BOTTOM SIDE" at 6246,-656.17 h60
  text ".TID" at 3224,-859.5 h60
  text "TID #:" at 3769.5,-859.5 h60
  text "TEXAS INSTRUMENTS" at 904.5,-1064.84 h60
  text ".Print_Time" at 2169,-1064.84 h60
  text ".Print_Date" at 2898,-1064.84 h60
  text "GENERATED    :" at 3767.5,-1064.84 h60
  text ".plot_File_Name" at 5440.5,-1064.84 h60
  text "PLOT NAME =" at 6246,-1064.84 h60
M9 Title Sheet:
  drawing of 57 lines, arcs and shapes, not listed
  text "1" at 739.84,8036.5 h70
  text "2" at 3235.5,8036.5 h70
  text "3" at 5724.84,8036.5 h70
  text "4" at 8231.51,8036.5 h70
  text "5" at 10730.5,8036.5 h70
  text "6" at 13235.5,8036.5 h70
  text "A" at -416.5,6893.5 h70
  text "A" at 14383.5,6893.5 h70
  text "B" at -416.5,4513.5 h70
  text "B" at 14383.5,4513.5 h70
  text "C" at -416.5,2138.5 h70
  text "C" at 14383.5,2138.5 h70
  text "PROJECT TITLE:" at 11343.5,277.5 h45
  text ".PRJ_Title" at 11393.5,144.17 h70
  text "DESIGNED FOR:" at 11343.5,-23.5 h45
  text ".PRJ_Customer" at 11393.5,-163.5 h70
  text "D" at -416.5,-231.5 h70
  text "D" at 14383.5,-231.5 h70
  text "FILE NAME:" at 11343.5,-323.5 h45
  text ".PCB_File_Name_No_Path" at 11393.5,-443.5 h70
  text "Texas Instruments (TI) and/or its licensors do not warrant the accuracy or completeness of this specification" at 6374,-605.34 h45
  text "ENGINEER:" at 11343.5,-613.5 h45
  text "LAYOUT BY:" at 12848.5,-613.5 h45
  text "or any information contained therein. TI and/or its licensors do not warrant that this design will meet" at 6329.01,-718 h45
  text ".PRJ_Engineer" at 11393.5,-768.49 h70
  text ".PCB_Layout" at 12899,-768.49 h70
  text "the specifications, will be suitable for your application or fit for any particular purpose, or will operate in" at 6329.01,-830.67 h45
  text ".Layer_Name" at 577,-858.49 h60
  text "ALTIUM DESIGNER VERSION:" at 12848.5,-923.5 h45
  text "an implementation. TI and/or its licensors do not warrant that the design is production worthy. You should" at 6329.01,-943.33 h45
  text "completely validate and test your design implementation to confirm the system functionality for your application." at 6374,-1056 h45
  text ".print_Scale" at 11393.5,-1056.83 h70
  text ".Application_BuildNumber" at 12899,-1056.83 h70
  text "1" at 739.84,-1263.5 h70
  text "2" at 3235.5,-1263.5 h70
  text "3" at 5724.84,-1263.5 h70
  text "4" at 8231.51,-1263.5 h70
  text "5" at 10730.5,-1263.5 h70
  text "6" at 13235.5,-1263.5 h70
M10 Fab Notes:
  drawing of 189 lines, arcs and shapes, not listed
  text "DESIGN INFORMATION" at 12382.02,6356.17 h60
  text "MIN. TRACK WIDTH:" at 11737.46,6224.05 h60
  text "6" at 12833.7,6224.05 h60
  text "MIL" at 12988.46,6224.05 h60
  text "MIN. CLEARANCE:" at 11737.46,6099.92 h60
  text "6" at 12833.7,6099.92 h60
  text "MIL" at 12988.46,6099.92 h60
  text "19.685" at 12631.34,5977.79 h60
  text "MIN. VIA PAD SIZE:" at 11737.46,5975.8 h60
  text "MIL" at 12988.46,5975.8 h60
  text "0.05mm (2MIL)" at 12432.46,5845.9 h60
  text "MINIMUM ANNULAR RING" at 11408.23,5837.67 h60
  text "EXTERNAL" at 13140.46,5837.67 h60
  text "PER" at 11608.23,5727.55 h60
  text "IPC-D-275 CLASS 2 LEVEL C" at 11828.23,5727.54 h60
  text "MIL, HOLES" at 13316.46,5627.07 h60
  text "+/-" at 12924,5618.48 h60
  text "+/-" at 13778,5618.48 h60
  text "REGISTRATION TOLERANCES:" at 11408.23,5617.42 h60
  text "METAL" at 12608,5617.42 h60
  text "5" at 13184.2,5617.42 h60
  text "3" at 14017.2,5617.42 h60
  text "MIL" at 14133.46,5617.42 h60
  text "HOLE SIZE TOLERANCE (UNLESS OTHERWISE SPECIFIED):" at 11408.23,5519.1 h60
  text "+/-" at 13778,5516.23 h60
  text "3" at 14017.2,5515.17 h60
  text "MIL" at 14133.46,5515.17 h60
  text "MATERIAL:" at 11333.46,5377.52 h60
  text "FR-4 High Tg" at 12319.9,5249 h60
  text "X" at 12175.46,5241.01 h60
  text "FR-4" at 11754.46,5236.49 h60
  text "OTHER" at 13242.46,5236.49 h60
  text "62 MIL (1.6mm) +/-10%" at 12074.56,5093.46 h60
  text "X" at 11954.46,5091.01 h60
  text "THICKNESS:" at 11408.23,5085.24 h60
  text "OTHER" at 13359.46,5085.24 h60
  text "TOLERANCE:" at 11408.23,4946.92 h60
  text "X" at 12256.46,4946.92 h60
  text "ANSI IPC-6012 TYPE 3 CLASS 2" at 12434.48,4946.92 h60
  text "OTHER +/-" at 12434.46,4802.73 h60
  text "BOW & TWIST:" at 11408.23,4657.54 h60
  text "X" at 12256.46,4657.54 h60
  text "ANSI IPC-6012 TYPE 3 CLASS 2" at 12434.48,4657.54 h60
  text "OTHER +/-" at 12434.46,4510.85 h60
  text "DRILLING:" at 11333.46,4380.23 h60
  text "NC_DRILL FILES" at 13094.46,4275.04 h60
  text "REFERENCE:" at 11408.23,4271.1 h60
  text "X" at 12065.46,4271.01 h60
  text "AS SHOWN" at 12243.46,4271.1 h60
  text "X" at 12966.46,4271.1 h60
  text "OTHER" at 13392.46,4128.85 h60
  text "PTH COPPER THICKNESS:" at 11407.91,4125.32 h60
  text "X" at 12547.14,4125.32 h60
  text "20-30 um" at 12675.14,4125.32 h60
  text "BOARD FINISH:" at 11333.46,3977.73 h60
  text "SILKSCREEN:" at 11488.68,3867.6 h60
  text "X" at 12446.46,3867.6 h60
  text "TOP" at 12563.46,3867.6 h60
  text "X" at 12948.43,3867.6 h60
  text "BOTTOM" at 13074.46,3867.6 h60
  text "SILKSCREEN COLOR:" at 11488.68,3712.41 h60
  text "X" at 12445.46,3712.41 h60
  text "WHITE" at 12563.46,3712.41 h60
  text "OTHER" at 13074.46,3712.41 h60
  text "X" at 12576.46,3568.96 h60
  text "GREEN" at 12694.46,3568.96 h60
  text "OTHER" at 13312.46,3568.96 h60
  text "SOLDER RESIST COLOR:" at 11488.68,3562.1 h60
  text "MATTE" at 12694.46,3414.71 h60
  text "SEMI-GLOSS" at 13312,3414.07 h60
  text "IMMERSION GOLD (ENIG)" at 12394.46,3241.94 h60
  text "ENEPIG" at 13732,3234.72 h60
  text "SURFACE FINISH:" at 11333.46,3233.72 h60
  text "X" at 12216.46,3233.72 h60
  text "IMM. TIN/SILVER OR EQUIV" at 11663,3096.4 h60
  text "OTHER" at 13094.46,3092.47 h60
  text "ARRAY/PANEL:" at 11333.46,2937.09 h60
  text "CUT AND TRIM PER M1 BOARD OUTLINE" at 12394.46,2928.87 h60
  text "N.C. ROUTE" at 12394.46,2792.9 h60
  text "X" at 13082.46,2792.9 h60
  text "V. SCORE" at 13260.46,2792.9 h60
  text "CERTIFICATION:" at 11333.46,2663.77 h60
  text "MATERIALS AND WORKMANSHIP FOR ALL PCBS" at 12058.46,2663.77 h60
  text "TO MEET OR EXCEED THE REQUIREMENTS OF:" at 12058.46,2569.71 h60
  text "X" at 11695.97,2441.08 h60
  text "ANSI IPC-A-600F CLASS ->" at 11823.96,2441.08 h60
  text "X" at 13471.97,2441.08 h60
  text "2" at 13581.96,2441.08 h60
  text "1" at 13266.96,2439.58 h60
  text "3" at 13935.96,2439.58 h60
  text "X" at 12507.97,2293.39 h60
  text "RoHS" at 12635.96,2293.39 h60
  text "OTHER" at 13280.36,2293.39 h60
  text "PER ORDER" at 13677.42,2293.39 h60
  text "ALL BOARDS MUST MEET OR EXCEED UL94-V0 REQUIREMENTS." at 11361,2139.57 h60
  text "PCB MUST BEAR THE UL94V-0 UL REGISTERED MATERIAL ID NUMBER" at 11361,2023.5 h60
  text "ADDITIONAL REQUIREMENTS:" at 11333.46,1854.08 h60
  text "MICROSECTION:" at 11408.23,1746.95 h60
  text "YES" at 12313.96,1746.95 h60
  text "REQUIRED" at 13175.46,1602.62 h60
  text "BARE BOARD ELEC. TEST:" at 11408.23,1599.76 h60
  text "NONE" at 12713.96,1599.76 h60
  text "X" at 13057.46,1599.76 h60
  text "PER ORDER" at 13767.46,1599.76 h60
  text "X" at 11464.66,1446.94 h60
  text "VIAS REQUIRE NON-CONDUCTIVE FILL AND PLANARIZE" at 11576.38,1394.82 h59
  text "XX MIL VIAS REQUIRE CONDUCTIVE FILL AND PLANARIZE" at 11584.38,1290.84 h60
  text "OUTER XX MIL TRACES REQUIRE 50 OHM SINGLE-ENDED IMPEDANCE" at 11583.39,1127.46 h58
  text "X" at 1023.31,892.84 h60
  text "LAYER 2 & 3 (INNER LAYERS) XX MIL WIDE, XX MIL SPACE / TRACES REQUIRE 100 OHM DIFFERENTIAL IMPEDANCE" at 11575.39,891.74 h60
  text "X" at 1077.36,719.4 h60
  text ".Layer_Name" at 577,-858.49 h60
M11 Gerber Information:
  lines w10: -292,-930.17 6308,-930.17 ; -292,-726.83 6310,-726.83 ; -292,-523.5 -292,-1133.5 3713,-1133.5 6310,-1133.5 6310,-523.5 -291.5,-523.5 -291.5,-1133.5 1284,-1133.5 ; 2173,-1133.5 2173,-523.5 ; 3440,-726.83 3440,-523.5 ; 4280,-726.83 4280,-523.5 ; 4902,-1140 4902,-937.17
  text "ALL ARTWORK VIEWED FROM TOP SIDE" at -228.5,-655.67 h60
  text "BOARD #:" at 2248,-655.67 h60
  text ".PRJ_Number" at 2793.5,-655.67 h60
  text "REV:" at 3638,-655.67 h60
  text ".PCB_Rev" at 3929.5,-655.67 h60
  text "SVN REV:" at 4476,-655.67 h60
  text ".VersionControl_RevNumber" at 4982,-655.67 h60
  text "LAYER NAME =" at -228.5,-858.49 h60
  text "TID #:" at 2248,-859 h60
  text ".TID" at 2793.5,-859 h60
  text "PLOT NAME =" at -228.5,-1064.34 h60
  text ".plot_File_Name" at 577,-1064.34 h60
  text "GENERATED    :" at 2250,-1064.34 h60
  text ".Print_Date" at 3119.5,-1064.34 h60
  text ".Print_Time" at 3848.5,-1064.34 h60
  text "TEXAS INSTRUMENTS" at 5113,-1064.34 h60
M12 Stackup:
  drawing of 399 lines, arcs and shapes, not listed
  text "Layer" at 6795.61,7854.8 h60
  text "Name" at 7205.52,7854.8 h60
  text "Material" at 8145.26,7854.8 h60
  text "Thickness" at 9005.03,7854.8 h60
  text "Constant" at 9654.87,7854.8 h60
  text "Board Layer Stack" at 10224.73,7854.8 h60
  text "Top Overlay" at 7205.52,7734.8 h60
  text "Top Solder" at 7205.52,7614.8 h60
  text "Solder Resist" at 8145.26,7614.8 h60
  text "0.50mil" at 9005.03,7614.8 h60
  text "3.5" at 9654.87,7614.8 h60
  text "1" at 6795.61,7494.8 h60
  text "Top Layer" at 7205.52,7494.8 h60
  text "2.80mil" at 9005.03,7494.8 h60
  text "Dielectric 1" at 7205.52,7374.8 h60
  text "FR-4 High Tg" at 8145.26,7374.8 h60
  text "7.00mil" at 9005.03,7374.8 h60
  text "4.2" at 9654.87,7374.8 h60
  text "2" at 6795.61,7254.8 h60
  text "Signal Layer 1" at 7205.52,7254.8 h60
  text "1.40mil" at 9005.03,7254.8 h60
  text "Dielectric 2" at 7205.52,7134.8 h60
  text "FR-4 High Tg" at 8145.26,7134.8 h60
  text "14.00mil" at 9005.03,7134.8 h60
  text "4.2" at 9654.87,7134.8 h60
  text "3" at 6795.61,7014.8 h60
  text "Signal Layer 2" at 7205.52,7014.8 h60
  text "1.40mil" at 9005.03,7014.8 h60
  text "Dielectric 4" at 7205.52,6894.8 h60
  text "FR-4 High Tg" at 8145.26,6894.8 h60
  text "8.20mil" at 9005.03,6894.8 h60
  text "4.2" at 9654.87,6894.8 h60
  text "4" at 6795.61,6774.8 h60
  text "Signal Layer 3" at 7205.52,6774.8 h60
  text "1.40mil" at 9005.03,6774.8 h60
  text "Dielectric 5" at 7205.52,6654.8 h60
  text "FR-4 High Tg" at 8145.26,6654.8 h60
  text "14.00mil" at 9005.03,6654.8 h60
  text "4.2" at 9654.87,6654.8 h60
  text "5" at 6795.61,6534.8 h60
  text "Signal Layer 4" at 7205.52,6534.8 h60
  text "1.40mil" at 9005.03,6534.8 h60
  text "Dielectric 3" at 7205.52,6414.8 h60
  text "FR-4 High Tg" at 8145.26,6414.8 h60
  text "7.00mil" at 9005.03,6414.8 h60
  text "4.2" at 9654.87,6414.8 h60
  text "6" at 6795.61,6294.8 h60
  text "Bottom Layer" at 7205.52,6294.8 h60
  text "2.80mil" at 9005.03,6294.8 h60
  text "Bottom Solder" at 7205.52,6174.8 h60
  text "Solder Resist" at 8145.26,6174.8 h60
  text "0.50mil" at 9005.03,6174.8 h60
  text "3.5" at 9654.87,6174.8 h60
  text "Bottom Overlay" at 7205.52,6054.8 h60
  text "Total board thickness:" at 6795.61,5934.8 h60
  text "62.40mil" at 9005.03,5934.8 h60
  text ".Layer_Name" at 577,-858.49 h60
M13 Component Bodies Top:
  text ".Layer_Name" at 577,-858.49 h60
M14 Component Bodies Bottom:
  text ".Layer_Name" at 577,-858.49 h60
M15 Courtyards Top:
  text ".Layer_Name" at 577,-858.49 h60
M16 Courtyards Bottom:
  text ".Layer_Name" at 577,-858.49 h60
Drill Drawing:
  circle w10: c6363.72,2841.64 r16.58
  circle w10: c6363.72,2841.64 r27.63
  circle w10: c6363.72,2220.04 r27.63
  lines w10: 6336.09,1943.78 6363.72,1957.59 6391.34,1943.78 6377.53,1971.4 6391.34,1999.03 6363.72,1985.22 6336.09,1999.03 6349.9,1971.4 6336.09,1943.78 ; 6336.09,2123.35 6391.34,2123.35 6363.72,2068.1 6336.09,2123.35 ; 6336.09,2330.55 6349.9,2330.55 6363.72,2316.74 6377.53,2330.55 6391.34,2330.55 6377.53,2344.36 6391.34,2358.18 6377.53,2358.18 6363.72,2371.99 6349.9,2358.18 6336.09,2358.18 6349.9,2344.36 6336.09,2330.55 ; 6336.09,2441.06 6336.09,2454.87 6349.9,2468.68 6336.09,2482.5 6336.09,2496.31 6349.9,2496.31 6363.72,2482.5 6377.53,2496.31 6391.34,2496.31 6391.34,2482.5 6377.53,2468.68 6391.34,2454.87 6391.34,2441.06 6377.53,2441.06 6363.72,2454.87 6349.9,2441.06 6336.09,2441.06 ; 6336.09,2565.38 6391.34,2565.38 6391.34,2620.63 6336.09,2620.63 6336.09,2565.38 ; 6336.09,2703.51 6349.9,2703.51 6349.9,2689.7 6377.53,2689.7 6377.53,2703.51 6391.34,2703.51 6391.34,2731.14 6377.53,2731.14 6377.53,2744.95 6349.9,2744.95 6349.9,2731.14 6336.09,2731.14 6336.09,2703.51 ; 6336.09,2938.34 6391.34,2938.34 6391.34,2993.59 6336.09,2993.59 6336.09,2938.34 ; 6336.09,3090.28 6363.72,3062.66 6391.34,3090.28 6363.72,3117.91 6336.09,3090.28 ; 6347.14,2576.43 6380.29,2576.43 6380.29,2609.58 6347.14,2609.58 6347.14,2576.43
  lines w12: 6286,1906.48 9517.21,1906.48 ; 6286,3149.68 9517.21,3149.68 ; 6623.85,1782.16 6623.85,3274 ; 6955.9,1782.16 6955.9,3274 ; 7592.27,1782.16 7592.27,3274 ; 7851.36,1782.16 7851.36,3274 ; 8226.5,1782.16 8226.5,3274 ; 8950.83,1782.16 8950.83,3274 ; 6286,1782.16 9517.21,1782.16 9517.21,3274 6286,3274 6286,1782.16
  text "Symbol" at 6360.59,3186.98 h72
  text "Quantity" at 6661.14,3186.98 h72
  text "Finished Hole Size" at 6993.2,3186.98 h72
  text "Plated" at 7629.57,3186.98 h72
  text "Hole Type" at 7888.66,3186.98 h72
  text "Drill Layer Pair" at 8263.79,3186.98 h72
  text "Hole Tolerance" at 8988.12,3186.98 h72
  text "18" at 6661.14,3062.66 h60
  text "7.87mil (0.200mm)" at 6993.2,3062.66 h60
  text "PTH" at 7629.57,3062.66 h60
  text "Round" at 7888.66,3062.66 h60
  text "Top Layer - Bottom Layer" at 8263.79,3062.66 h60
  text "1093" at 6661.14,2938.34 h60
  text "8.00mil (0.203mm)" at 6993.2,2938.34 h60
  text "PTH" at 7629.57,2938.34 h60
  text "Round" at 7888.66,2938.34 h60
  text "Top Layer - Bottom Layer" at 8263.79,2938.34 h60
  text "232" at 6661.14,2814.02 h60
  text "16.00mil (0.406mm)" at 6993.2,2814.02 h60
  text "PTH" at 7629.57,2814.02 h60
  text "Round" at 7888.66,2814.02 h60
  text "Top Layer - Bottom Layer" at 8263.79,2814.02 h60
  text "15" at 6661.14,2689.7 h60
  text "33.07mil (0.840mm)" at 6993.2,2689.7 h60
  text "PTH" at 7629.57,2689.7 h60
  text "Round" at 7888.66,2689.7 h60
  text "Top Layer - Bottom Layer" at 8263.79,2689.7 h60
  text "16" at 6661.14,2565.38 h60
  text "39.37mil (1.000mm)" at 6993.2,2565.38 h60
  text "PTH" at 7629.57,2565.38 h60
  text "Round" at 7888.66,2565.38 h60
  text "Top Layer - Bottom Layer" at 8263.79,2565.38 h60
  text "10" at 6661.14,2441.06 h60
  text "40.00mil (1.016mm)" at 6993.2,2441.06 h60
  text "PTH" at 7629.57,2441.06 h60
  text "Round" at 7888.66,2441.06 h60
  text "Top Layer - Bottom Layer" at 8263.79,2441.06 h60
  text "64" at 6661.14,2316.74 h60
  text "45.28mil (1.150mm)" at 6993.2,2316.74 h60
  text "PTH" at 7629.57,2316.74 h60
  text "Round" at 7888.66,2316.74 h60
  text "Top Layer - Bottom Layer" at 8263.79,2316.74 h60
  text "2" at 6661.14,2192.42 h60
  text "118.11mil (3.000mm)" at 6993.2,2192.42 h60
  text "PTH" at 7629.57,2192.42 h60
  text "Round" at 7888.66,2192.42 h60
  text "Top Layer - Bottom Layer" at 8263.79,2192.42 h60
  text "6" at 6661.14,2068.1 h60
  text "125.98mil (3.200mm)" at 6993.2,2068.1 h60
  text "PTH" at 7629.57,2068.1 h60
  text "Round" at 7888.66,2068.1 h60
  text "Top Layer - Bottom Layer" at 8263.79,2068.1 h60
  text "4" at 6661.14,1943.78 h60
  text "270.00mil (6.858mm)" at 6993.2,1943.78 h60
  text "PTH" at 7629.57,1943.78 h60
  text "Round" at 7888.66,1943.78 h60
  text "Top Layer - Bottom Layer" at 8263.79,1943.78 h60
  text "1460 Total" at 6661.14,1819.46 h60
  text ".Layer_Name" at 577,-858.49 h60
M17 Embedded Cavity:
  text ".Layer_Name" at 577,-858.49 h60
M18 Embedded Assembly:
  text ".Layer_Name" at 577,-858.49 h60
M19 Embedded Keepout:
  text ".Layer_Name" at 577,-858.49 h60

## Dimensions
0,0 to 5010,0 on M2 Board Dimensions
0,0 to 0,3800 on M2 Board Dimensions
0,-400 to 1000,-400 on M2 Board Dimensions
